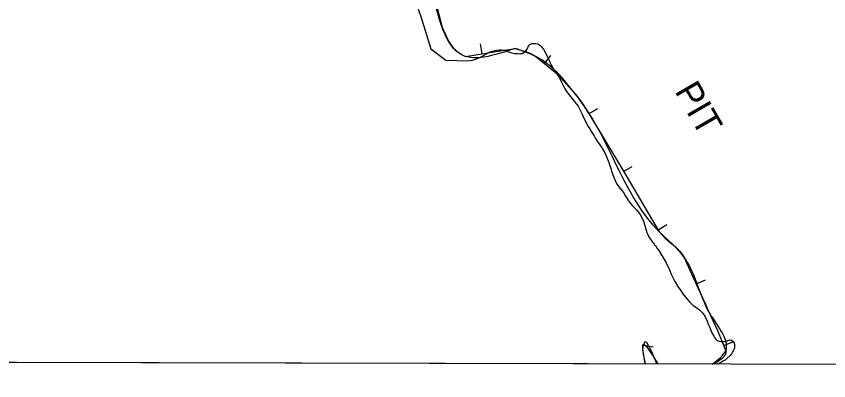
# Model space of a CAD drawing. Extents: x 3177185 to 3215018, y 812988 to 838321.
# Drawn here: x 3193354 to 3195360, y 818326 to 819225 of the extents above; entities that cross this region are included whole.
import ezdxf

# ---------------------------------------------------------------- set-up
doc = ezdxf.new("R2010")
doc.units = 0
for name, color, linetype in [('V-BORW-IDEN', 7, 'Continuous'), ('V-BORW-LINE', 7, 'Continuous'), ('V-GRID-FRAM', 7, 'Continuous'), ('V-SITE-VEGE', 7, 'Continuous')]:
    doc.layers.add(name, color=color, linetype=linetype)

msp = doc.modelspace()

# ---------------------------------------------------------------- linework, layer by layer
at = {"layer": 'V-BORW-LINE'}
for p, q in [((3194504.3, 819132.9), (3194500.3, 819157.5)), ((3194657.9, 819108.7), (3194673.7, 819128.1)), ((3194768.2, 818985.1), (3194789.7, 818997.9)), ((3194853.4, 818841.9), (3194874.9, 818854.7)), ((3194938.5, 818698.7), (3194960, 818711.5)), ((3195032.6, 818564.9), (3195055.4, 818575.2)), ((3194901.9, 818413.7), (3194926.6, 818409.7)), ((3195100.4, 818412.8), (3195123.6, 818422.1))]:
    msp.add_line(p, q, dxfattribs=at)
for points in [[(3194382.9, 819287.2), (3194404.6, 819199.8), (3194421, 819164), (3194432.1, 819147.8), (3194447.3, 819133.8), (3194463.4, 819126.3), (3194584.7, 819145.8)], [(3194584.7, 819145.8), (3194611.5, 819138.4), (3194624.5, 819133.1), (3194637, 819125.7), (3194689.7, 819082.8), (3194734, 819033.9), (3194749.4, 819013.3), (3194763.9, 818992.3), (3194852.9, 818842.8), (3194941.6, 818693.6), (3194956.1, 818677.5), (3194981.9, 818656.6), (3194993.5, 818645.3), (3195002.1, 818631.9), (3195025.2, 818581.2), (3195048.2, 818530.4), (3195055.3, 818514.8), (3195062.3, 818499.3), (3195085.5, 818449.7), (3195105.5, 818400.3), (3195106, 818394), (3195104, 818388.9), (3195096.6, 818380.9), (3195076.5, 818367.3)], [(3194935.9, 818367.6), (3194922.9, 818397.3), (3194910.7, 818420.7), (3194905.9, 818422.5), (3194902.2, 818415.3), (3194900.4, 818404.3), (3194905.7, 818367.7)]]:
    msp.add_lwpolyline(points, dxfattribs=at)
for points in [[(3194584.7, 819145.8), (3194447.3, 819133.8), (3194404.6, 819199.8), (3194370.1, 819313.4), (3194215, 819487.3), (3194145.9, 819581.9), (3194097.2, 819676.7), (3194042.5, 819943.4), (3194160.3, 819974.7), (3194208.8, 820009.4), (3194249.9, 820024.5), (3194281, 820046.5), (3194446.7, 820147), (3194502.5, 820176.3), (3194643.3, 820226.6), (3194678.6, 820230.1), (3194691.3, 820209.9), (3194714.7, 820155.9), (3194815.7, 820194), (3194832.8, 820210.5), (3194832.6, 820243.6), (3194842.9, 820252.6), (3194935.3, 820275.8), (3194949, 820268.4), (3194960, 820224.8), (3194976.6, 820189), (3194995.1, 820162.4), (3195014.2, 820127.7)], [(3195014.2, 820127.7), (3195051.2, 820036.5), (3195079.1, 820023.1), (3195095.7, 820005.5), (3195110.9, 819937.1), (3195175.2, 819834.1), (3195197, 819771), (3195216.4, 819742.6), (3195236, 819732.1), (3195343.1, 819557.8), (3195386.4, 819443.9), (3195423.7, 819413.9), (3195435.2, 819377.3), (3195508.3, 819247.2), (3195522.8, 819188.1), (3195531.4, 819165.4), (3195561.3, 819137), (3195612, 819024.1), (3195671.6, 818940.9), (3195804.7, 818724.1), (3195856.6, 818587.8), (3195891.3, 818540.3), (3195947, 818433), (3195956.5, 818375.3), (3195958.6, 818365.3)], [(3195072.5, 818367.3), (3195105.5, 818400.3), (3195062.3, 818499.3), (3195048.2, 818530.4), (3195002.1, 818631.9), (3194941.6, 818693.6), (3194763.9, 818992.3), (3194734, 819033.9), (3194637, 819125.7), (3194584.7, 819145.8)], [(3194907.2, 818367.7), (3194902.2, 818415.3), (3194937.7, 818367.6)]]:
    msp.add_spline(points, degree=3, dxfattribs=at)
at = {"layer": 'V-GRID-FRAM'}
msp.add_lwpolyline([(3181402.4, 836586.1), (3212801.6, 836513), (3212767.2, 818326.1), (3181352.2, 818399.3), (3181402.4, 836586.1)], dxfattribs=at)
at = {"layer": 'V-SITE-VEGE'}
for p, q in [((3194313.1, 819339.2), (3194352.8, 819224.9)), ((3194352.8, 819224.9), (3194377.7, 819144.9)), ((3194377.7, 819144.9), (3194414.3, 819116.9)), ((3194615.2, 819144.1), (3194619.9, 819153.9)), ((3194619.9, 819153.9), (3194622, 819155.9)), ((3194622, 819155.9), (3194626.8, 819158)), ((3194626.8, 819158), (3194630.4, 819158)), ((3194630.4, 819158), (3194636.9, 819157.7)), ((3194636.9, 819157.7), (3194643.4, 819156.1)), ((3194643.4, 819156.1), (3194647.4, 819153.3)), ((3194647.4, 819153.3), (3194650.3, 819150.5)), ((3194650.3, 819150.5), (3194655.6, 819143.7)), ((3194495.7, 819122.4), (3194501.8, 819125.2)), ((3194501.8, 819125.2), (3194509.8, 819129.8)), ((3194509.8, 819129.8), (3194523.9, 819137.2)), ((3194523.9, 819137.2), (3194529.9, 819139.3)), ((3194529.9, 819139.3), (3194539.6, 819141.4)), ((3194539.6, 819141.4), (3194546.5, 819142.7)), ((3194546.5, 819142.7), (3194551.3, 819142.7)), ((3194551.3, 819142.7), (3194559, 819141.6)), ((3194559, 819141.6), (3194571.6, 819136.8)), ((3194571.6, 819136.8), (3194574, 819136)), ((3194574, 819136), (3194580.9, 819134.1)), ((3194580.9, 819134.1), (3194585, 819133.7)), ((3194585, 819133.7), (3194591.4, 819133.4)), ((3194591.4, 819133.4), (3194597.5, 819132.6)), ((3194597.5, 819132.6), (3194599.5, 819133)), ((3194599.5, 819133), (3194602.8, 819133.5)), ((3194602.8, 819133.5), (3194605.6, 819134.7)), ((3194605.6, 819134.7), (3194612.4, 819139.6)), ((3194612.4, 819139.6), (3194615.2, 819144.1)), ((3194655.6, 819143.7), (3194665.1, 819126.8)), ((3194665.1, 819126.8), (3194668, 819119.9)), ((3194414.3, 819116.9), (3194468.7, 819115.2)), ((3194468.7, 819115.2), (3194480.4, 819116.6)), ((3194480.4, 819116.6), (3194488.9, 819119.5)), ((3194488.9, 819119.5), (3194495.7, 819122.4)), ((3194668, 819119.9), (3194672.1, 819110.7)), ((3194672.1, 819110.7), (3194674.2, 819107.1)), ((3194674.2, 819107.1), (3194678.7, 819097.8)), ((3194678.7, 819097.8), (3194682, 819092.6)), ((3194682, 819092.6), (3194695.1, 819072.9)), ((3194695.1, 819072.9), (3194700, 819062.8)), ((3194700, 819062.8), (3194703.7, 819056)), ((3194703.7, 819056), (3194708.7, 819046)), ((3194708.7, 819046), (3194712.8, 819039.5)), ((3194712.8, 819039.5), (3194731.6, 819015.8)), ((3194731.6, 819015.8), (3194734.1, 819012.6)), ((3194734.1, 819012.6), (3194741, 819003)), ((3194741, 819003), (3194745.6, 818995.4)), ((3194745.6, 818995.4), (3194751.3, 818983.7)), ((3194751.3, 818983.7), (3194754.6, 818975.2)), ((3194754.6, 818975.2), (3194766.2, 818953.5)), ((3194766.2, 818953.5), (3194770.3, 818947.1)), ((3194770.3, 818947.1), (3194774.4, 818940.3)), ((3194774.4, 818940.3), (3194780.5, 818930.2)), ((3194780.5, 818930.2), (3194784.2, 818923.8)), ((3194784.2, 818923.8), (3194788.3, 818917.3)), ((3194788.3, 818917.3), (3194799, 818902.5)), ((3194799, 818902.5), (3194800.6, 818900.5)), ((3194800.6, 818900.5), (3194802.3, 818896.9)), ((3194802.3, 818896.9), (3194806.8, 818888)), ((3194806.8, 818888), (3194810.1, 818880.8)), ((3194810.1, 818880.8), (3194816.7, 818864.7)), ((3194816.7, 818864.7), (3194822.6, 818846.9)), ((3194822.6, 818846.9), (3194823.8, 818844.1)), ((3194823.8, 818844.1), (3194826.7, 818834.4)), ((3194826.7, 818834.4), (3194834.6, 818815.9)), ((3194834.6, 818815.9), (3194837.5, 818810.3)), ((3194837.5, 818810.3), (3194844.4, 818801.4)), ((3194844.4, 818801.4), (3194847.3, 818798.6)), ((3194847.3, 818798.6), (3194849.7, 818794.6)), ((3194849.7, 818794.6), (3194854.6, 818787.8)), ((3194854.6, 818787.8), (3194857.5, 818782.6)), ((3194857.5, 818782.6), (3194861.6, 818776.1)), ((3194861.6, 818776.1), (3194865.3, 818769.7)), ((3194865.3, 818769.7), (3194867.8, 818766.5)), ((3194867.8, 818766.5), (3194874.7, 818758.5)), ((3194874.7, 818758.5), (3194885.3, 818747.3)), ((3194885.3, 818747.3), (3194889, 818743.2)), ((3194889, 818743.2), (3194896, 818734)), ((3194896, 818734), (3194897.2, 818731.6)), ((3194897.2, 818731.6), (3194902.2, 818720.7)), ((3194902.2, 818720.7), (3194905.1, 818711.9)), ((3194905.1, 818711.9), (3194907.2, 818703.4)), ((3194907.2, 818703.4), (3194910.5, 818691.7)), ((3194910.5, 818691.7), (3194912.2, 818688.1)), ((3194912.2, 818688.1), (3194914.2, 818684.1)), ((3194914.2, 818684.1), (3194915.9, 818681.2)), ((3194915.9, 818681.2), (3194919.2, 818676.4)), ((3194919.2, 818676.4), (3194924.9, 818667.6)), ((3194924.9, 818667.6), (3194927.4, 818665.6)), ((3194927.4, 818665.6), (3194928.6, 818663.2)), ((3194928.6, 818663.2), (3194929.8, 818661.6)), ((3194929.8, 818661.6), (3194931.9, 818659.6)), ((3194931.9, 818659.6), (3194936, 818652.7)), ((3194936, 818652.7), (3194940.5, 818647.5)), ((3194940.5, 818647.5), (3194957.7, 818618.6)), ((3194957.7, 818618.6), (3194966.8, 818600.1)), ((3194966.8, 818600.1), (3194970.9, 818589.2)), ((3194970.9, 818589.2), (3194974.2, 818582.8)), ((3194974.2, 818582.8), (3194977.5, 818575.5)), ((3194977.5, 818575.5), (3194980, 818570.7)), ((3194980, 818570.7), (3194985.7, 818562.2)), ((3194985.7, 818562.2), (3194986.6, 818559.8)), ((3194986.6, 818559.8), (3194989.8, 818555.4)), ((3194989.8, 818555.4), (3194993.9, 818549.4)), ((3194993.9, 818549.4), (3194997.6, 818544.6)), ((3194997.6, 818544.6), (3195002.5, 818537.3)), ((3195002.5, 818537.3), (3195011.1, 818526.9)), ((3195011.1, 818526.9), (3195015.2, 818521.3)), ((3195015.2, 818521.3), (3195017.3, 818519.7)), ((3195017.3, 818519.7), (3195020.1, 818516.5)), ((3195020.1, 818516.5), (3195025.4, 818512.1)), ((3195025.4, 818512.1), (3195031.9, 818507.3)), ((3195031.9, 818507.3), (3195040.9, 818500.9)), ((3195040.9, 818500.9), (3195045, 818496.9)), ((3195045, 818496.9), (3195047.4, 818494.1)), ((3195047.4, 818494.1), (3195052.3, 818487.7)), ((3195052.3, 818487.7), (3195055.2, 818483.7)), ((3195055.2, 818483.7), (3195059.8, 818472.8)), ((3195059.8, 818472.8), (3195061.8, 818468.4)), ((3195061.8, 818468.4), (3195063.1, 818464.3)), ((3195063.1, 818464.3), (3195066, 818457.5)), ((3195066, 818457.5), (3195068.5, 818451)), ((3195068.5, 818451), (3195070.5, 818446.2)), ((3195070.5, 818446.2), (3195075.9, 818436.2)), ((3195075.9, 818436.2), (3195077.9, 818432.5)), ((3195077.9, 818432.5), (3195080, 818429.7)), ((3195080, 818429.7), (3195082.8, 818426.9)), ((3195082.8, 818426.9), (3195085.3, 818425.7)), ((3195085.3, 818425.7), (3195089.7, 818423.8)), ((3195089.7, 818423.8), (3195093.8, 818423)), ((3195093.8, 818423), (3195101.9, 818423.1)), ((3195101.9, 818423.1), (3195104.7, 818423.5)), ((3195104.7, 818423.5), (3195109.5, 818424.8)), ((3195109.5, 818424.8), (3195115.2, 818426.8)), ((3195115.2, 818426.8), (3195119.6, 818426.5)), ((3195119.6, 818426.5), (3195122.1, 818424.9)), ((3195122.1, 818424.9), (3195125.7, 818421.7)), ((3195127.1, 818406.7), (3195124.3, 818399.8)), ((3195125.7, 818421.7), (3195126.6, 818419.3)), ((3195126.6, 818419.3), (3195127, 818414)), ((3195127, 818414), (3195127.1, 818406.7)), ((3195116.3, 818388.8), (3195109.1, 818381.9)), ((3195119.5, 818392.9), (3195116.3, 818388.8)), ((3195122.7, 818397.8), (3195119.5, 818392.9)), ((3195124.3, 818399.8), (3195122.7, 818397.8)), ((3195083.3, 818367.3), (3193169.7, 818371.8)), ((3195095.5, 818372.1), (3195083.3, 818367.3)), ((3195101.9, 818375.8), (3195095.5, 818372.1)), ((3195104.3, 818377), (3195101.9, 818375.8)), ((3195109.1, 818381.9), (3195104.3, 818377))]:
    msp.add_line(p, q, dxfattribs=at)

# ---------------------------------------------------------------- texts
at = {"layer": 'V-BORW-IDEN'}
msp.add_text('PIT', height=64, rotation=299.9817, dxfattribs=at).set_placement((3194978.3, 819040.6))

doc.saveas('drawing.dxf')
